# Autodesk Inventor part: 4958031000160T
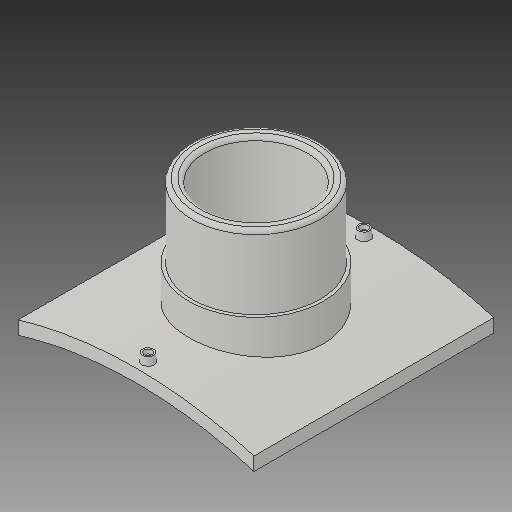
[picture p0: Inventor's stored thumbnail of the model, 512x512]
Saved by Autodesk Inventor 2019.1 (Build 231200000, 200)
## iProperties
Created: 2017-10
Part Number: 4958031000160T
Material: Generic
Description: PLASSON BRANCH SADDLE  1000x160
Document SubType Name: Modeling
Designer: KIM
Mass: 2754.05 g
Surface Area: 3037.44 cm^2
Volume: 2754.05 cm^3
Density: 1 g/cm^3
Appearance: Default
Author: KIM
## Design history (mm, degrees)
derived "495803.ipt"
feature "Solid1::495803.ipt"
tag "TaggingFeature1"
body "Solid1"
other parameters: "d1" = 16, "d2" = 295, "d4" = 0, "d12" = 525.6, "d13" = 14, "d14" = 135, "d16" = 5 deg, "d18" = 4, "d19" = 14, "d20" = 0, "d21" = 3, "d22" = 0, "d23" = 647, "d24" = 168, "d25" = 16, "d26" = 128, "d28" = 0, "d29" = 9.6, "d31" = 0, "d32" = 65.5, "d33" = 0, "d37" = 91.7, "d38" = 0, "d39" = 5, "B_" = 295, "H_" = 131, "x_" = 16, "D_" = 16
